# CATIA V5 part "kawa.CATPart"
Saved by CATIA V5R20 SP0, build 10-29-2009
Part number: 卡瓦
Material "Steel": density 7860 kg/m3, Young's modulus 2e+11 Pa, Poisson ratio 0.266, thermal expansion 1.17e-05 1/K
Bounding box of the stored display mesh (mm): x -44 to 74, y -43.999 to 13.684, z -30 to 30
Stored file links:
  F:\CATIA\XLW\kawa.CATPart
  D:\CATIA\intel_a\startup\materials\Catalog.CATMaterial
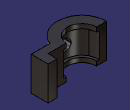
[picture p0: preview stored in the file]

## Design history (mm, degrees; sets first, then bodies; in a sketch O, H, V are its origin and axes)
Body1 (main body), material "Steel"
  Sketch1 on xy-plane, origin (0, 0, 0), H (1, 0, 0), V (0, 1, 0)
    arc A1 centre (0, 0) radius 26 from (-26, 0) to (25.8966, -2.316) ccw
    arc A2 centre (0, 0) radius 44 from (-44, 0) to (40.863, -16.316) ccw
    line L1 (25.8966, -2.316) -> (58, -2.316)
    line L2 (58, -2.316) -> (58, 13.684)
    line L3 (58, 13.684) -> (74, 13.684)
    line L4 (74, 13.684) -> (74, -16.316)
    line L5 (74, -16.316) -> (40.863, -16.316)
    line L6 (-26, 0) -> (-44, 0)
    point P6 (-44, 0)
    point P7 (-44, 0)
    radius A2 = 44
    radius A1 = 26
    length L4 = 30
    length L3 = 16
    length L2 = 16
    distance O L4 = 74
    horizontal: L1 H, L3 H, L5 H, L6 H
    vertical: L2 V, L4 V
    coincidence: P6 A2, L6 P7, P6 P7
  Pad1: profile Sketch1, direction (0, 0, 1), length 30, mirrored extent
  Sketch2 on face of Pad1 from Sketch1.L6, origin (0, 0, 0), H (-1, 0, 0), V (0, 0, 1)
    point P1 (25.5859, 0)
    line L1 (30.5859, 22) -> (30.5859, -22)
    line L2 (30.5859, -22) -> (20.5859, -22)
    line L3 (20.5859, -22) -> (20.5859, 22)
    line L4 (20.5859, 22) -> (30.5859, 22)
    length L1 = 44
    length L4 = 10
    coincidence: P1 H
    vertical: L1 V, L3 V
    horizontal: L2 H, L4 H
    equidistance: L1 L3 P1, L2 L4 P1
  Groove1: profile Sketch2, axis axis of face of Pad1 from Sketch1.A1, angle 360
  Sketch3 on zx-plane, origin (0, 0, 0), H (-1, 0, 0), V (0, 0, 1)
    circle A1 centre (0, 0) radius 10
    reference projected line E1 (-25.8966, -30) -> (26, -30) from edge [start face of Pad1 | face of Pad1 from Sketch1.A1]
    radius A1 = 10
    distance H E1 = 30
  Pocket1: profile Sketch3, direction (0, -1, 0), through (limit type 3)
